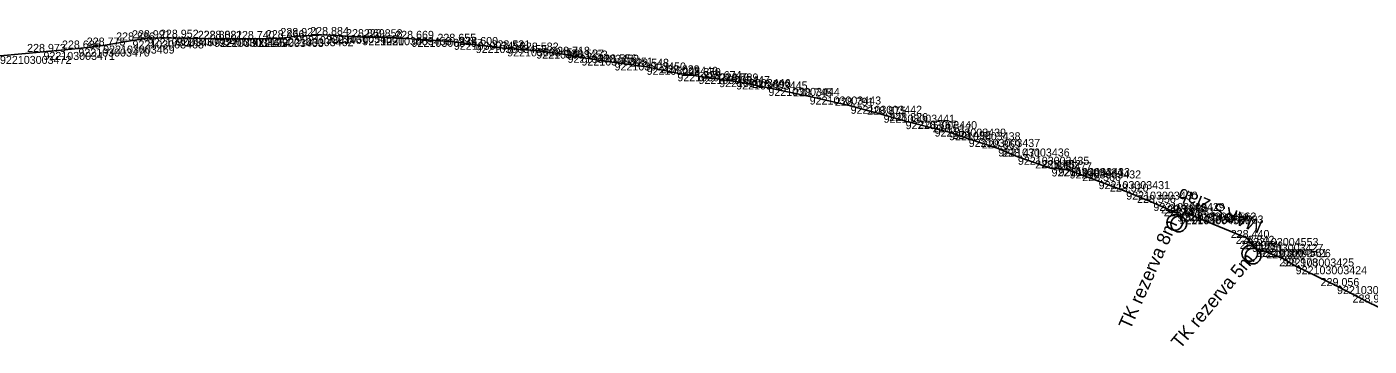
# Model space of a CAD drawing. Extents: x -771047 to -756200, y -1053876 to -1046520.
# Drawn here: x -770008.9 to -769807.6, y -1050162.5 to -1050114.7 of the extents above; entities that cross this region are included whole.
import ezdxf

# ---------------------------------------------------------------- set-up
doc = ezdxf.new("R2010")
doc.units = 0
for name, color, linetype in [('Vrstva 32', 7, 'Continuous'), ('Vrstva 33', 7, 'Continuous'), ('Vrstva 60', 7, 'Continuous'), ('Vrstva 61', 7, 'Continuous')]:
    doc.layers.add(name, color=color, linetype=linetype)

msp = doc.modelspace()

# ---------------------------------------------------------------- linework, layer by layer
at = {"layer": 'Vrstva 32'}
for points in [[(-769836.36, -1050142.62), (-769839.96, -1050141.05), (-769844.03, -1050139.35), (-769848.17, -1050137.77), (-769852.51, -1050136.17), (-769854.19, -1050135.82), (-769855.23, -1050135.87), (-769860.27, -1050134.12), (-769863.22, -1050132.88), (-769867.65, -1050131.45), (-769870.59, -1050130.45), (-769872.76, -1050129.9), (-769877.11, -1050128.78), (-769880.41, -1050127.82), (-769885.36, -1050126.48), (-769891.5, -1050125.09), (-769897.69, -1050123.8), (-769902.52, -1050122.84), (-769905.07, -1050122.49), (-769908.17, -1050122.02), (-769911.34, -1050121.61), (-769915.95, -1050120.64), (-769920.76, -1050119.99), (-769925.72, -1050119.25), (-769927.81, -1050118.84), (-769932.5, -1050118.21), (-769936.86, -1050117.88), (-769941.58, -1050117.37), (-769944.86, -1050116.89), (-769951.2, -1050116.45), (-769955.9, -1050116.21), (-769958.57, -1050116.2), (-769963.95, -1050115.87), (-769968.51, -1050116.03), (-769970.61, -1050116.35), (-769975.08, -1050116.47), (-769980.03, -1050116.43), (-769980.8, -1050116.45), (-769986.48, -1050116.28), (-769990.76, -1050116.36), (-769993.05, -1050116.69), (-769997.44, -1050117.46), (-770001.16, -1050117.9), (-770006.4, -1050118.41), (-770012.92, -1050119.01)], [(-769835.23, -1050142.48), (-769836.04, -1050143.04), (-769836.36, -1050142.62)], [(-769835.23, -1050142.48), (-769834.16, -1050142.92), (-769825.91, -1050146.3), (-769825.17, -1050147.17)], [(-769824.07, -1050147.98), (-769824.56, -1050147.92), (-769825.17, -1050147.17)], [(-769802.85, -1050158.28), (-769807.64, -1050155.97), (-769812.42, -1050153.5), (-769818.62, -1050150.53), (-769820.57, -1050149.36), (-769824.07, -1050147.98)]]:
    msp.add_lwpolyline(points, dxfattribs=at)
for centre in [(-769836.76, -1050143.97), (-769836.16, -1050144.21), (-769825.51, -1050148.61), (-769825, -1050149.01)]:
    msp.add_circle(centre, 1.17, dxfattribs=at)
at = {"layer": 'Vrstva 33'}
msp.add_lwpolyline([(-769835.23, -1050142.48), (-769825.91, -1050146.3), (-769825.17, -1050147.17)], dxfattribs=at)
at = {"layer": 'Vrstva 60'}
for p, q in [((-769990.76, -1050116.36), (-769990.76, -1050116.36)), ((-769986.48, -1050116.28), (-769986.48, -1050116.28)), ((-769970.61, -1050116.35), (-769970.61, -1050116.35)), ((-769968.51, -1050116.03), (-769968.51, -1050116.03)), ((-769963.95, -1050115.87), (-769963.95, -1050115.87)), ((-769958.57, -1050116.2), (-769958.57, -1050116.2)), ((-769955.9, -1050116.21), (-769955.9, -1050116.21)), ((-770001.16, -1050117.9), (-770001.16, -1050117.9)), ((-769997.44, -1050117.46), (-769997.44, -1050117.46)), ((-769993.05, -1050116.69), (-769993.05, -1050116.69)), ((-769980.8, -1050116.45), (-769980.8, -1050116.45)), ((-769980.03, -1050116.43), (-769980.03, -1050116.43)), ((-769975.08, -1050116.47), (-769975.08, -1050116.47)), ((-769951.2, -1050116.45), (-769951.2, -1050116.45)), ((-769944.86, -1050116.89), (-769944.86, -1050116.89)), ((-769941.58, -1050117.37), (-769941.58, -1050117.37)), ((-769936.86, -1050117.88), (-769936.86, -1050117.88)), ((-769932.5, -1050118.21), (-769932.5, -1050118.21)), ((-770006.4, -1050118.41), (-770006.4, -1050118.41)), ((-769927.81, -1050118.84), (-769927.81, -1050118.84)), ((-769925.72, -1050119.25), (-769925.72, -1050119.25)), ((-769920.76, -1050119.99), (-769920.76, -1050119.99)), ((-769915.95, -1050120.64), (-769915.95, -1050120.64)), ((-769911.34, -1050121.61), (-769911.34, -1050121.61)), ((-769908.17, -1050122.02), (-769908.17, -1050122.02)), ((-769905.07, -1050122.49), (-769905.07, -1050122.49)), ((-769902.52, -1050122.84), (-769902.52, -1050122.84)), ((-769897.69, -1050123.8), (-769897.69, -1050123.8)), ((-769891.5, -1050125.09), (-769891.5, -1050125.09)), ((-769885.36, -1050126.48), (-769885.36, -1050126.48)), ((-769880.41, -1050127.82), (-769880.41, -1050127.82)), ((-769877.11, -1050128.78), (-769877.11, -1050128.78)), ((-769872.76, -1050129.9), (-769872.76, -1050129.9)), ((-769870.59, -1050130.45), (-769870.59, -1050130.45)), ((-769867.65, -1050131.45), (-769867.65, -1050131.45)), ((-769863.22, -1050132.88), (-769863.22, -1050132.88)), ((-769860.27, -1050134.12), (-769860.27, -1050134.12)), ((-769855.23, -1050135.87), (-769855.23, -1050135.87)), ((-769854.19, -1050135.82), (-769854.19, -1050135.82)), ((-769852.51, -1050136.17), (-769852.51, -1050136.17)), ((-769848.17, -1050137.77), (-769848.17, -1050137.77)), ((-769844.03, -1050139.35), (-769844.03, -1050139.35)), ((-769839.96, -1050141.05), (-769839.96, -1050141.05)), ((-769835.23, -1050142.48), (-769835.23, -1050142.48)), ((-769836.36, -1050142.62), (-769836.36, -1050142.62)), ((-769836.04, -1050143.04), (-769836.04, -1050143.04)), ((-769834.16, -1050142.92), (-769834.16, -1050142.92)), ((-769825.91, -1050146.3), (-769825.91, -1050146.3)), ((-769825.17, -1050147.17), (-769825.17, -1050147.17)), ((-769824.56, -1050147.92), (-769824.56, -1050147.92)), ((-769824.07, -1050147.98), (-769824.07, -1050147.98)), ((-769820.57, -1050149.36), (-769820.57, -1050149.36)), ((-769818.62, -1050150.53), (-769818.62, -1050150.53)), ((-769812.42, -1050153.5), (-769812.42, -1050153.5)), ((-769807.64, -1050155.97), (-769807.64, -1050155.97))]:
    msp.add_line(p, q, dxfattribs=at)

# ---------------------------------------------------------------- texts
at = {"layer": 'Vrstva 32'}
for s, rotation, p in [('TK rezerva 8m', 66.028, (-769843.43, -1050160.15)), ('TK rezerva 5m', 49.9333, (-769835.95, -1050163.03))]:
    msp.add_text(s, height=2, rotation=rotation, dxfattribs=at).set_placement(p)
at = {"layer": 'Vrstva 33'}
msp.add_text('MARS žlab', height=2, rotation=157.7359, dxfattribs=at).set_placement((-769823.41, -1050143.82))
at = {"layer": 'Vrstva 60'}
for s, p in [('922103003467', (-769990.76, -1050117.56)), ('922103003466', (-769986.48, -1050117.48)), ('922103003462', (-769970.61, -1050117.55)), ('922103003461', (-769968.51, -1050117.23)), ('922103003460', (-769963.95, -1050117.07)), ('922103003459', (-769958.57, -1050117.4)), ('922103003458', (-769955.9, -1050117.41)), ('922103003471', (-770006.4, -1050119.61)), ('922103003470', (-770001.16, -1050119.1)), ('922103003469', (-769997.44, -1050118.66)), ('922103003468', (-769993.05, -1050117.89)), ('922103003465', (-769980.8, -1050117.65)), ('922103003464', (-769980.03, -1050117.63)), ('922103003463', (-769975.08, -1050117.67)), ('922103003457', (-769951.2, -1050117.65)), ('922103003456', (-769944.86, -1050118.09)), ('922103003455', (-769941.58, -1050118.57)), ('922103003454', (-769936.86, -1050119.08)), ('922103003453', (-769932.5, -1050119.41)), ('922103003472', (-770012.92, -1050120.21)), ('922103003452', (-769927.81, -1050120.04)), ('922103003451', (-769925.72, -1050120.45)), ('922103003450', (-769920.76, -1050121.19)), ('922103003449', (-769915.95, -1050121.84)), ('922103003448', (-769911.34, -1050122.81)), ('922103003447', (-769908.17, -1050123.22)), ('922103003446', (-769905.07, -1050123.69)), ('922103003445', (-769902.52, -1050124.04)), ('922103003444', (-769897.69, -1050125)), ('922103003443', (-769891.5, -1050126.29)), ('922103003442', (-769885.36, -1050127.68)), ('922103003441', (-769880.41, -1050129.02)), ('922103003440', (-769877.11, -1050129.98)), ('922103003439', (-769872.76, -1050131.1)), ('922103003438', (-769870.59, -1050131.65)), ('922103003437', (-769867.65, -1050132.65)), ('922103003436', (-769863.22, -1050134.08)), ('922103003435', (-769860.27, -1050135.32)), ('922103003434', (-769855.23, -1050137.07)), ('922103003433', (-769854.19, -1050137.02)), ('922103003432', (-769852.51, -1050137.37)), ('922103003431', (-769848.17, -1050138.97)), ('922103003430', (-769844.03, -1050140.55)), ('922103003429', (-769839.96, -1050142.25)), ('922103004562', (-769835.23, -1050143.68)), ('922103003428', (-769836.36, -1050143.82)), ('922103004563', (-769836.04, -1050144.24)), ('922103004783', (-769834.16, -1050144.12)), ('922103004553', (-769825.91, -1050147.5)), ('922103003427', (-769825.17, -1050148.37)), ('922103004561', (-769824.56, -1050149.12)), ('922103003426', (-769824.07, -1050149.18)), ('922103003425', (-769820.57, -1050150.56)), ('922103003424', (-769818.62, -1050151.73)), ('922103004782', (-769812.42, -1050154.7))]:
    msp.add_text(s, height=1.2, dxfattribs=at).set_placement(p)
at = {"layer": 'Vrstva 61'}
for s, p in [('228.775', (-769999.9, -1050117.46)), ('228.886', (-769995.5, -1050116.69)), ('228.991', (-769993.12, -1050116.36)), ('228.952', (-769988.93, -1050116.28)), ('228.808', (-769983.25, -1050116.45)), ('228.821', (-769982.39, -1050116.43)), ('228.740', (-769977.53, -1050116.47)), ('228.866', (-769973.06, -1050116.35)), ('228.921', (-769970.87, -1050116.03)), ('228.884', (-769966.4, -1050115.87)), ('228.869', (-769961.02, -1050116.2)), ('228.858', (-769958.35, -1050116.21)), ('228.669', (-769953.65, -1050116.45)), ('228.655', (-769947.32, -1050116.89)), ('228.600', (-769944.03, -1050117.37)), ('228.973', (-770008.85, -1050118.41)), ('228.685', (-770003.62, -1050117.9)), ('228.531', (-769939.21, -1050117.88)), ('228.582', (-769934.95, -1050118.21)), ('228.718', (-769930.26, -1050118.84)), ('228.527', (-769928.17, -1050119.25)), ('228.556', (-769923.21, -1050119.99)), ('228.548', (-769918.4, -1050120.64)), ('228.629', (-769913.8, -1050121.61)), ('228.679', (-769910.62, -1050122.02)), ('228.674', (-769907.52, -1050122.49)), ('228.789', (-769904.98, -1050122.84)), ('228.890', (-769900.14, -1050123.8)), ('228.745', (-769893.96, -1050125.09)), ('228.791', (-769887.71, -1050126.48)), ('228.875', (-769882.86, -1050127.82)), ('228.826', (-769879.56, -1050128.78)), ('228.767', (-769875.21, -1050129.9)), ('228.517', (-769873.04, -1050130.45)), ('228.492', (-769870.1, -1050131.45)), ('228.869', (-769865.67, -1050132.88)), ('228.471', (-769862.63, -1050134.12)), ('228.475', (-769857.68, -1050135.87)), ('228.482', (-769856.64, -1050135.82)), ('228.477', (-769854.96, -1050136.17)), ('228.566', (-769850.62, -1050137.77)), ('228.520', (-769846.48, -1050139.35)), ('228.556', (-769842.41, -1050141.05)), ('228.737', (-769838.82, -1050142.62)), ('228.571', (-769838.4, -1050143.04)), ('228.830', (-769837.68, -1050142.48)), ('228.931', (-769836.52, -1050142.92)), ('228.440', (-769828.36, -1050146.3)), ('228.842', (-769827.61, -1050147.17)), ('229.074', (-769827.01, -1050147.92)), ('228.984', (-769826.52, -1050147.98)), ('228.922', (-769823.02, -1050149.36)), ('228.978', (-769821.08, -1050150.53)), ('229.056', (-769814.88, -1050153.5)), ('228.954', (-769810.09, -1050155.97))]:
    msp.add_text(s, height=1.2, dxfattribs=at).set_placement(p)

doc.saveas('drawing.dxf')
